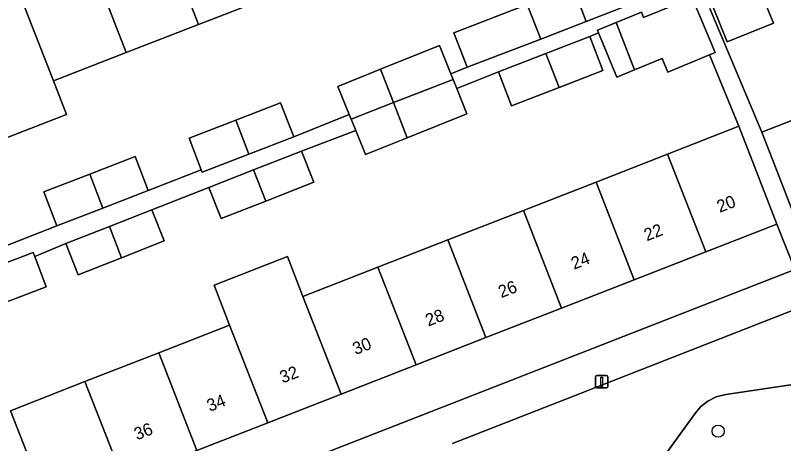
# Model space of a CAD drawing. Extents: x 159680 to 160786, y 387323 to 388340.
# Drawn here: x 160064.8 to 160126.9, y 387705.7 to 387740.3 of the extents above; entities that cross this region are included whole.
import ezdxf

# ---------------------------------------------------------------- set-up
doc = ezdxf.new("R2010")
doc.units = 0
for name, color, linetype in [('IMGEO_Boom', 7, 'Continuous'), ('IMGEO_Erf', 7, 'Continuous'), ('IMGEO_Groenvoorziening', 7, 'Continuous'), ('IMGEO_Lichtmast', 7, 'Continuous'), ('IMGEO_Pand', 7, 'Continuous'), ('IMGEO_Pand_nummerreeks', 7, 'Continuous'), ('IMGEO_Voetpad_open', 7, 'Continuous')]:
    doc.layers.add(name, color=color, linetype=linetype)

msp = doc.modelspace()

# ---------------------------------------------------------------- linework, layer by layer
at = {"layer": 'IMGEO_Boom'}
msp.add_circle((160121.565, 387706.746), 0.489, dxfattribs=at)
at = {"layer": 'IMGEO_Erf'}
for points in [[(160109.842, 387742.628), (160110.908, 387739.846), (160115.136, 387741.493)], [(160120.902, 387740.895), (160125.095, 387730.896), (160131.174, 387733.276), (160137.147, 387735.615), (160142.914, 387737.872), (160148.737, 387740.152), (160154.794, 387742.524)], [(160124.924, 387742.503), (160126.039, 387739.715), (160122.286, 387738.214), (160121.171, 387741.002)], [(160085.652, 387741.976), (160079.568, 387739.609), (160073.73, 387737.338), (160067.843, 387735.048), (160068.893, 387732.348), (160063.049, 387730.075)], [(160063.713, 387721.604), (160068.113, 387723.336), (160067.051, 387726.08), (160070.772, 387727.52), (160074.447, 387728.942), (160075.509, 387726.197), (160079.792, 387727.854), (160078.803, 387730.411), (160082.577, 387731.871), (160086.199, 387733.272), (160087.261, 387730.527), (160091.752, 387732.337), (160090.84, 387734.599), (160094.284, 387735.988), (160099.037, 387737.905), (160099.957, 387735.624), (160101.277, 387736.156), (160100.211, 387738.938), (160106.143, 387741.211)], [(160064.358, 387708.4), (160070.388, 387710.753), (160076.346, 387713.078), (160082.077, 387715.314), (160080.821, 387718.532), (160086.749, 387720.846), (160088.005, 387717.628), (160094.072, 387719.995), (160099.711, 387722.196), (160105.825, 387724.582), (160111.702, 387726.875), (160117.482, 387729.131), (160123.244, 387731.379), (160120.861, 387737.151), (160117.49, 387735.759), (160117.032, 387736.867), (160114.82, 387735.954), (160113.377, 387735.359), (160111.902, 387738.932), (160111.197, 387738.641), (160112.258, 387735.896), (160108.717, 387734.525), (160104.863, 387733.034), (160103.801, 387735.779), (160100.441, 387734.423), (160101.257, 387732.401), (160096.437, 387730.457), (160093.06, 387729.095), (160092.271, 387731.05), (160087.887, 387729.379), (160088.876, 387726.858), (160084.998, 387725.335), (160081.391, 387723.92), (160080.401, 387726.441), (160075.797, 387724.634), (160076.786, 387722.113), (160073.347, 387720.763), (160069.832, 387719.384), (160068.843, 387721.905), (160066.327, 387720.851), (160067.252, 387718.4), (160061.428, 387716.201)], [(160060.074, 387718.864), (160066.203, 387721.178), (160066.327, 387720.851), (160068.843, 387721.905), (160072.363, 387723.286), (160075.797, 387724.634), (160080.401, 387726.441), (160084.013, 387727.859), (160087.887, 387729.379), (160092.271, 387731.05), (160091.902, 387731.964), (160091.752, 387732.337), (160087.261, 387730.527), (160083.644, 387729.128), (160079.865, 387727.666), (160079.792, 387727.854), (160075.509, 387726.197), (160071.839, 387724.777), (160068.113, 387723.336), (160063.713, 387721.604)], [(160063.763, 387704.855), (160067.164, 387696.141), (160068.881, 387696.811), (160067.439, 387700.504), (160065.622, 387705.162), (160064.358, 387708.4)]]:
    msp.add_lwpolyline(points, dxfattribs=at)
msp.add_lwpolyline([(160127.764, 387719.796), (160126.325, 387723.483), (160120.563, 387721.235), (160114.783, 387718.979), (160108.906, 387716.686), (160102.792, 387714.3), (160097.153, 387712.099), (160091.086, 387709.732), (160085.158, 387707.419), (160079.427, 387705.182), (160073.469, 387702.857), (160067.439, 387700.504), (160068.881, 387696.811)], close=True, dxfattribs=at)
at = {"layer": 'IMGEO_Groenvoorziening'}
for points in [[(160128.251, 387716.753), (160116.68, 387712.231), (160100.09, 387705.736)], [(160119.673, 387708.148), (160120.152, 387708.72), (160120.74, 387709.179), (160121.41, 387709.507), (160122.18, 387709.694), (160131.248, 387711.047), (160129.329, 387716.088)], [(160133.564, 387704.662), (160131.248, 387711.047), (160122.18, 387709.694), (160121.41, 387709.507), (160120.74, 387709.179), (160120.152, 387708.72), (160119.673, 387708.148), (160113.688, 387699.856), (160106.239, 387698.209), (160102.286, 387697.335), (160103.941, 387693.11)], [(160099.519, 387704.401), (160102.286, 387697.335), (160106.239, 387698.209), (160113.688, 387699.856), (160119.673, 387708.148)]]:
    msp.add_lwpolyline(points, dxfattribs=at)
at = {"layer": 'IMGEO_Lichtmast'}
for p, q in [((160111.656, 387710.335), (160111.656, 387711.135)), ((160111.656, 387711.135), (160111.656, 387710.335)), ((160111.756, 387711.235), (160112.546, 387711.235)), ((160112.546, 387711.235), (160111.756, 387711.235)), ((160112.646, 387711.135), (160112.646, 387710.335)), ((160112.646, 387710.335), (160112.646, 387711.135)), ((160112.546, 387710.235), (160111.756, 387710.235)), ((160111.756, 387710.235), (160112.546, 387710.235))]:
    msp.add_line(p, q, dxfattribs=at)
msp.add_lwpolyline([(160112.076, 387711.11), (160112.226, 387711.11), (160112.226, 387710.36), (160112.076, 387710.36), (160112.076, 387711.11)], dxfattribs=at)
for centre, start, end in [((160111.756, 387711.135), 90, 180), ((160111.756, 387711.135), 90, 180), ((160112.546, 387711.135), 0, 90), ((160112.546, 387711.135), 360, 90), ((160111.756, 387710.335), 180, 270), ((160111.756, 387710.335), 180, 270), ((160112.546, 387710.335), 270, 0), ((160112.546, 387710.335), 270, 0)]:
    msp.add_arc(centre, 0.1, start, end, dxfattribs=at)
at = {"layer": 'IMGEO_Pand'}
for points in [[(160079.568, 387739.609), (160085.652, 387741.976), (160082.587, 387749.856), (160076.503, 387747.49)], [(160076.503, 387747.49), (160070.664, 387745.218), (160073.73, 387737.338), (160079.568, 387739.609)], [(160067.843, 387735.048), (160073.73, 387737.338), (160070.664, 387745.218), (160064.777, 387742.928)], [(160064.777, 387742.928), (160058.934, 387740.655), (160061.999, 387732.775), (160063.049, 387730.075), (160068.893, 387732.348), (160067.843, 387735.048)], [(160110.908, 387739.846), (160109.842, 387742.628), (160106.143, 387741.211), (160107.223, 387738.434)], [(160124.924, 387742.503), (160121.171, 387741.002), (160122.286, 387738.214), (160126.039, 387739.715)], [(160119.478, 387741.802), (160115.538, 387740.176), (160115.361, 387740.604), (160113.332, 387739.766), (160114.82, 387735.954), (160117.032, 387736.867), (160117.49, 387735.759), (160120.861, 387737.151), (160121.32, 387737.34)], [(160100.211, 387738.938), (160101.277, 387736.156), (160107.223, 387738.434), (160106.143, 387741.211)], [(160113.332, 387739.766), (160111.816, 387739.141), (160111.902, 387738.932), (160113.377, 387735.359), (160114.82, 387735.954)], [(160112.258, 387735.896), (160111.197, 387738.641), (160107.647, 387737.267), (160108.717, 387734.525)], [(160099.957, 387735.624), (160099.037, 387737.905), (160094.284, 387735.988), (160095.33, 387733.293), (160100.144, 387735.159)], [(160103.801, 387735.779), (160104.863, 387733.034), (160108.717, 387734.525), (160107.647, 387737.267)], [(160094.284, 387735.988), (160090.84, 387734.599), (160091.752, 387732.337), (160091.902, 387731.964), (160095.33, 387733.293)], [(160100.441, 387734.423), (160100.144, 387735.159), (160095.33, 387733.293), (160096.437, 387730.457), (160101.257, 387732.401)], [(160087.261, 387730.527), (160086.199, 387733.272), (160082.577, 387731.871), (160083.644, 387729.128)], [(160095.33, 387733.293), (160091.902, 387731.964), (160092.271, 387731.05), (160093.06, 387729.095), (160096.437, 387730.457)], [(160131.174, 387733.276), (160125.095, 387730.896), (160126.332, 387727.735), (160128.155, 387723.079), (160134.234, 387725.459)], [(160082.577, 387731.871), (160078.803, 387730.411), (160079.792, 387727.854), (160079.865, 387727.666), (160083.644, 387729.128)], [(160120.563, 387721.235), (160126.325, 387723.483), (160124.508, 387728.141), (160123.244, 387731.379), (160117.482, 387729.131)], [(160075.509, 387726.197), (160074.447, 387728.942), (160070.772, 387727.52), (160071.839, 387724.777)], [(160087.887, 387729.379), (160084.013, 387727.859), (160084.998, 387725.335), (160088.876, 387726.858)], [(160117.482, 387729.131), (160111.702, 387726.875), (160114.783, 387718.979), (160120.563, 387721.235)], [(160084.013, 387727.859), (160080.401, 387726.441), (160081.391, 387723.92), (160084.998, 387725.335)], [(160067.051, 387726.08), (160068.113, 387723.336), (160071.839, 387724.777), (160070.772, 387727.52)], [(160108.906, 387716.686), (160114.783, 387718.979), (160111.702, 387726.875), (160105.825, 387724.582)], [(160075.797, 387724.634), (160072.363, 387723.286), (160073.347, 387720.763), (160076.786, 387722.113)], [(160102.792, 387714.3), (160108.906, 387716.686), (160105.825, 387724.582), (160099.711, 387722.196)], [(160072.363, 387723.286), (160068.843, 387721.905), (160069.832, 387719.384), (160073.347, 387720.763)], [(160097.153, 387712.099), (160102.792, 387714.3), (160099.711, 387722.196), (160094.072, 387719.995)], [(160066.327, 387720.851), (160066.203, 387721.178), (160060.074, 387718.864), (160061.123, 387716.086), (160061.428, 387716.201), (160067.252, 387718.4)], [(160088.005, 387717.628), (160086.749, 387720.846), (160080.821, 387718.532), (160082.077, 387715.314), (160085.158, 387707.419), (160091.086, 387709.732)], [(160094.072, 387719.995), (160088.005, 387717.628), (160091.086, 387709.732), (160097.153, 387712.099)], [(160079.427, 387705.182), (160085.158, 387707.419), (160082.077, 387715.314), (160076.346, 387713.078)], [(160076.346, 387713.078), (160070.388, 387710.753), (160073.469, 387702.857), (160079.427, 387705.182)], [(160070.388, 387710.753), (160064.358, 387708.4), (160065.622, 387705.162), (160067.439, 387700.504), (160073.469, 387702.857)]]:
    msp.add_lwpolyline(points, close=True, dxfattribs=at)
at = {"layer": 'IMGEO_Voetpad_open'}
for points in [[(160205.143, 387750), (160183.527, 387741.562), (160182.349, 387741.102), (160129.215, 387720.362), (160127.764, 387719.796), (160068.881, 387696.811), (160067.164, 387696.141), (160045.929, 387687.852)], [(160115.136, 387741.493), (160110.908, 387739.846), (160107.223, 387738.434), (160101.277, 387736.156), (160099.957, 387735.624), (160100.144, 387735.159), (160100.441, 387734.423), (160103.801, 387735.779), (160107.647, 387737.267), (160111.197, 387738.641), (160111.902, 387738.932), (160111.816, 387739.141), (160113.332, 387739.766), (160115.361, 387740.604), (160115.538, 387740.176), (160119.478, 387741.802), (160121.32, 387737.34), (160120.861, 387737.151), (160123.244, 387731.379), (160124.508, 387728.141), (160126.325, 387723.483), (160127.764, 387719.796)], [(160128.155, 387723.079), (160126.332, 387727.735), (160125.095, 387730.896), (160120.902, 387740.895)], [(160100.09, 387705.736), (160116.68, 387712.231), (160128.251, 387716.753)]]:
    msp.add_lwpolyline(points, dxfattribs=at)

# ---------------------------------------------------------------- texts
at = {"layer": 'IMGEO_Pand_nummerreeks'}
for s, rotation, p in [('20', 21.31715, (160121.697, 387724.383)), ('22', 21.31715, (160115.804, 387722.083)), ('24', 21.31715, (160109.918, 387719.786)), ('26', 21.31715, (160104.03, 387717.488)), ('28', 21.31715, (160098.143, 387715.191)), ('30', 21.31715, (160092.254, 387712.893)), ('32', 21.31976, (160086.36, 387710.592)), ('34', 21.31715, (160080.475, 387708.296)), ('36', 21.31715, (160074.587, 387705.998))]:
    msp.add_text(s, height=1, rotation=rotation, dxfattribs=at).set_placement(p)

doc.saveas('drawing.dxf')
